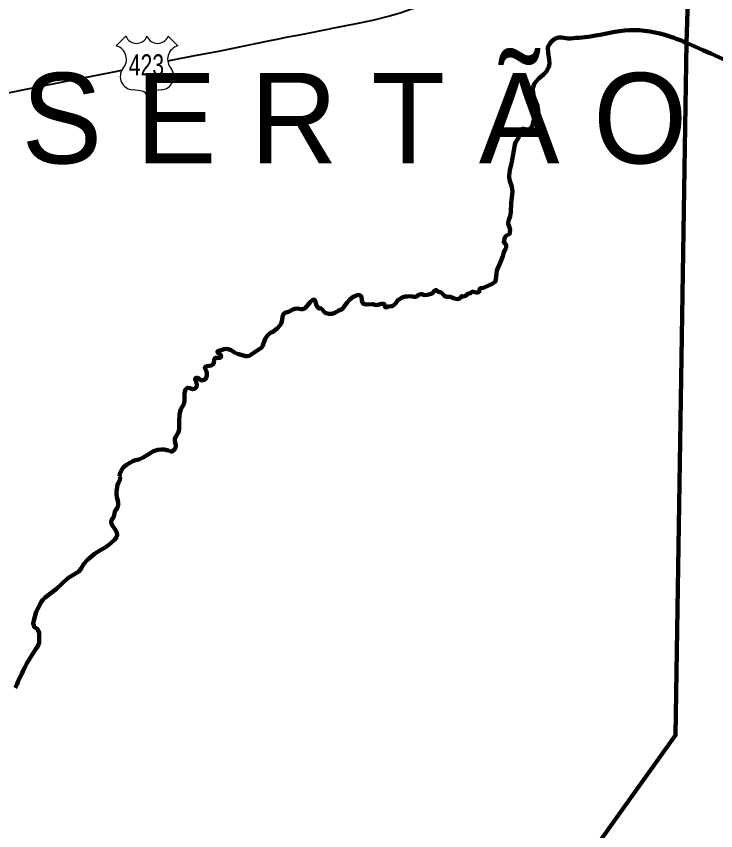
# Model space of a CAD drawing. Extents: x 553962 to 842807, y 8883888 to 9032388.
# Drawn here: x 626151 to 637742, y 8959925 to 8973416 of the extents above; entities that cross this region are included whole.
import ezdxf
from ezdxf.enums import TextEntityAlignment as Align

# ---------------------------------------------------------------- set-up
doc = ezdxf.new("R2010")
doc.units = 0
doc.header["$LTSCALE"] = 200
for name, color, linetype, lineweight in [('12', 7, 'Continuous', 25), ('24', 7, 'Continuous', 25), ('48', 7, 'Continuous', 25), ('9', 7, 'Continuous', 90)]:
    doc.layers.add(name, color=color, linetype=linetype, lineweight=lineweight)
doc.layers.add('13', color=7, linetype='Continuous')

msp = doc.modelspace()

# ---------------------------------------------------------------- linework, layer by layer
at = {"layer": '12', "lineweight": 40}
for points in [[(636526.5, 8974783.6), (636082.7, 8974635.6), (635662.2, 8974501.7), (635260.8, 8974371.9), (634884.1, 8974246.1), (634508.7, 8974119.3), (634143, 8973999.6), (633777.1, 8973878.8), (633411.3, 8973759), (633045.5, 8973640.3), (632701.6, 8973531.6), (632515, 8973468.2), (632359.8, 8973423.8), (632056.8, 8973345.2), (631756.7, 8973285.7), (631470.2, 8973228.1), (631226.1, 8973179.7), (631010.7, 8973135.2), (630810.4, 8973099.9), (630618.3, 8973063.5), (630498.6, 8973037.3), (630299.5, 8972998.9)], [(630299.5, 8972998.9), (629900.9, 8972917.2), (629502.3, 8972835.4), (629106.4, 8972761.7), (628714.6, 8972683.9), (628658.2, 8972671.9)], [(627892.1, 8972517.3), (627787.3, 8972497.2), (626527.3, 8972247.8), (625278.3, 8971995.4), (625208.3, 8971975.3), (624859.1, 8971919.6), (624586.2, 8971856.1), (624327.1, 8971807.6), (624078.9, 8971766.2), (623877.2, 8971718.8), (623688.2, 8971682.4)]]:
    msp.add_lwpolyline(points, dxfattribs=at)
at = {"layer": '24'}
for points in [[(635289.1, 8973046.9), (635193.3, 8973064.8), (635152.3, 8973065.7), (635121.8, 8973060.6), (635088.4, 8973049.6), (635061.3, 8973033.5), (635024.5, 8973002.4), (634997.2, 8972972.3), (634966.1, 8972918.2), (634961, 8972900.1), (634963.3, 8972809), (634982.5, 8972700.9), (634988.3, 8972634.8), (634977.1, 8972576.7), (634957, 8972536.6), (634931, 8972498.5), (634893.6, 8972457.3), (634810.8, 8972383.1), (634757.5, 8972324.9), (634734.8, 8972291.8), (634721.1, 8972258.8), (634713.2, 8972225.7), (634711, 8972195.6), (634723.7, 8972103.5), (634738.5, 8972051.5), (634787.3, 8971934.3), (634802.1, 8971867.3), (634801, 8971826.2), (634787, 8971787.1), (634735.3, 8971720.9), (634725.3, 8971693.9), (634707.4, 8971613.7), (634694.8, 8971588.7), (634670.6, 8971557.6), (634653, 8971546.5), (634625.3, 8971541.5), (634559.7, 8971552.4), (634539.5, 8971553.4), (634505.6, 8971527.3), (634489.3, 8971482.2), (634473.5, 8971402), (634424.6, 8971322.8), (634411, 8971288.8), (634363.8, 8971005.2), (634331.5, 8970867), (634319.9, 8970779.8), (634321.1, 8970743.8), (634328.9, 8970692.7), (634361.6, 8970589.6), (634374.7, 8970513.5), (634371.4, 8970461.4), (634350, 8970323.2), (634349.1, 8970169.9), (634336.1, 8970107.8), (634312.2, 8970046.7), (634303.6, 8970002.6), (634304.6, 8969985.6), (634333.8, 8969882.4), (634332.9, 8969828.3), (634324.3, 8969808.3), (634272.2, 8969782.2), (634248.5, 8969757.1), (634230.1, 8969676), (634268.6, 8969630), (634268.6, 8969569.3)], [(634268.6, 8969569.3), (634244.3, 8969539), (634226.1, 8969484.3), (634214, 8969441.9), (634171.5, 8969332.7), (634116.8, 8969205.3), (634098.6, 8969053.6), (634086.5, 8969017.2), (634039.3, 8968984.8)], [(634039.3, 8968984.8), (633892.2, 8968920.1), (633841.2, 8968911.2), (633829, 8968894.2), (633826.5, 8968860.1), (633814.7, 8968848.1), (633792.7, 8968839.1), (633772.6, 8968838), (633707.3, 8968856), (633679.2, 8968828.9), (633643, 8968822.8), (633597.4, 8968783.7), (633572.7, 8968776.6), (633532.2, 8968781.6), (633506.6, 8968748.5), (633477, 8968733.4), (633461.8, 8968732.4), (633415.1, 8968740.3), (633342.3, 8968771.2), (633285, 8968769.1), (633251.4, 8968778.1), (633194.6, 8968839.1), (633136, 8968858.1), (633110.7, 8968880), (633099.8, 8968882), (633077.7, 8968869), (633061.8, 8968841.9), (633034, 8968818.8), (632961, 8968800.7), (632917, 8968797.6), (632873.8, 8968812.6), (632857.7, 8968813.5), (632829.5, 8968806.5), (632784.3, 8968774.4), (632762.5, 8968768.3), (632743.5, 8968767.3), (632689.7, 8968778.2), (632635, 8968777.1), (632594.3, 8968772.1), (632546, 8968759), (632474, 8968715.8), (632441.1, 8968661.6), (632402.4, 8968626.5), (632375.7, 8968616.5), (632320, 8968608.4), (632276, 8968592.3), (632267.3, 8968594.3), (632260.3, 8968604.3), (632251.7, 8968645.3), (632234.7, 8968652.3), (632204.8, 8968654.2), (632145, 8968637.1), (632109, 8968631.1), (632058.6, 8968648), (631959.9, 8968641.8), (631914.2, 8968649.8), (631895.5, 8968662.8), (631887.1, 8968674.8), (631878, 8968708.8), (631869.8, 8968767.9), (631863.3, 8968783.9), (631842.8, 8968796.9), (631814.7, 8968800.9), (631735.7, 8968766.7), (631677.1, 8968724.5), (631636.5, 8968676.4), (631586.8, 8968606.2)], [(631586.8, 8968606.2), (631586.8, 8968606.2), (631566, 8968583.1), (631538.7, 8968561.1), (631495.2, 8968543), (631432.7, 8968503.8), (631386.3, 8968486.7), (631328.7, 8968484.6), (631284.8, 8968496.6), (631269.3, 8968505.5), (631202.2, 8968575.6), (631191.8, 8968578.5), (631168.3, 8968573.5), (631157.2, 8968578.5), (631126.3, 8968623.5), (631111.8, 8968681.6), (631101.9, 8968706.6), (631091.9, 8968716.6), (631075.5, 8968722.6), (631055.8, 8968713.5), (631019.8, 8968680.4), (630944.5, 8968589.2), (630924.7, 8968575.1), (630898.9, 8968567.1), (630870.7, 8968563), (630810.1, 8968573.9), (630771.4, 8968571.9), (630733.8, 8968558.8), (630662, 8968521.6), (630604.2, 8968505.5), (630582.5, 8968486.4), (630570.5, 8968464.4), (630552, 8968360.2), (630538.6, 8968328.1), (630519, 8968295), (630475.5, 8968245.9), (630400.9, 8968188.7), (630373.3, 8968178.6), (630353.6, 8968166.6), (630308.6, 8968122.4), (630276.4, 8968071.3), (630238.3, 8967960.1), (630219.6, 8967931), (630204, 8967915.9), (630110, 8967856.7), (630037.7, 8967805.5), (630008, 8967791.4), (629973.1, 8967784.4), (629952.7, 8967785.3), (629818.6, 8967822.2), (629765.8, 8967848.1), (629713, 8967885.1), (629664.5, 8967904.1), (629633.8, 8967907), (629598, 8967904), (629531.5, 8967879.8), (629496.2, 8967871.8), (629483.7, 8967859.7), (629486.2, 8967847.7), (629492.6, 8967840.7), (629540.7, 8967810.7), (629545.3, 8967784.7), (629540.8, 8967768.7), (629532.8, 8967760.6), (629522.4, 8967757.6), (629462.2, 8967760.5), (629444.6, 8967756.5), (629432.2, 8967733.4), (629423.8, 8967670.3), (629408.2, 8967648.3), (629382.3, 8967632.2), (629313.2, 8967622.1), (629285.3, 8967611), (629277.8, 8967603), (629278.1, 8967588), (629305.3, 8967533.9), (629310.7, 8967502.9), (629308.8, 8967461.8), (629293.1, 8967414.7), (629266.5, 8967393.6), (629234, 8967384.6), (629199.3, 8967395.5), (629158.3, 8967424.5), (629139.8, 8967426.5), (629123.2, 8967422.5), (629117.6, 8967414.4), (629118, 8967394.4), (629139.5, 8967343.4), (629144.7, 8967309.3), (629140.5, 8967289.3), (629122.5, 8967256.2), (629103.3, 8967245.2), (629075.3, 8967238.1), (629026.3, 8967257.1), (628994.8, 8967264), (628978.7, 8967255), (628957.3, 8967232.9), (628940.9, 8967175.8), (628937.1, 8967045.6), (628928.9, 8966993.5), (628879.5, 8966907.3)], [(628879.5, 8966907.3), (628856.2, 8966825.1), (628856.2, 8966825.1), (628847.9, 8966696.9), (628850.9, 8966584.7), (628846.8, 8966548.7), (628833.2, 8966513.6), (628795.6, 8966457.4), (628777.8, 8966417.3), (628777.8, 8966370.3), (628794.8, 8966312.2), (628795, 8966279.2), (628772.4, 8966240.1), (628724.9, 8966202.9), (628672.1, 8966222.8)], [(628672.1, 8966222.8), (628644.5, 8966231.7), (628607, 8966237.7), (628560.1, 8966237.6), (628499.1, 8966232.5), (628424.4, 8966210.3), (628380.7, 8966187.2), (628295.1, 8966129), (628244.3, 8966100.9), (628182.1, 8966074.8), (628126, 8966063.7), (628091.9, 8966052.6), (628032.2, 8966021.4), (627977.3, 8965986.3), (627925.1, 8965941.1), (627901.8, 8965910.1), (627866.5, 8965837.9), (627864.4, 8965796.7)], [(627864.4, 8965796.7), (627870.8, 8965773.8), (627867.2, 8965732.7), (627839, 8965684.6), (627827.1, 8965654.5), (627811.8, 8965541.3), (627811.5, 8965505.3), (627817.4, 8965449.2), (627838.1, 8965372.1), (627841, 8965321), (627826.7, 8965271.9), (627798.1, 8965236.8), (627783.4, 8965207.8), (627766.8, 8965123.6), (627733.2, 8965082.5), (627726.4, 8965067.5), (627723.3, 8965046.4), (627728.3, 8965015.4), (627739.7, 8964986.4), (627792.5, 8964916.3), (627811.7, 8964876.3), (627823.6, 8964830.2), (627816, 8964796.2)], [(627816, 8964796.2), (627816, 8964796.2), (627780.2, 8964746.1), (627680.5, 8964655.8), (627612, 8964609.6), (627536.8, 8964566.4), (627449.5, 8964509.2), (627333.7, 8964414.8), (627272.4, 8964348.6), (627225, 8964267.4), (627185.5, 8964217.3), (627032.1, 8964127.9), (627004.7, 8964107.8), (626815.8, 8963934.3), (626629.8, 8963789.7), (626590.1, 8963751.6), (626566.7, 8963720.5), (626506, 8963608.3), (626480.1, 8963551.1), (626439.9, 8963406.8), (626430.6, 8963358.8), (626441.2, 8963331.8), (626448.8, 8963299.7), (626457.1, 8963293.7), (626491.3, 8963272.5), (626505.7, 8963251), (626515.9, 8963242.8), (626529.7, 8963201.7), (626531.3, 8963131.3), (626529.2, 8963109.8), (626529.5, 8963038.6), (626501.7, 8962971.9), (626473.9, 8962938.6), (626318.3, 8962688.6), (626296, 8962638.6), (626262.7, 8962577.5), (626240.4, 8962522), (626212.7, 8962460.8), (626174.8, 8962393.8), (626164.1, 8962350.8), (626134.9, 8962291.6)]]:
    msp.add_lwpolyline(points, dxfattribs=at)
at = {"layer": '48'}
for p, q in [((627808.4, 8972926.9), (627968.3, 8973086.8)), ((628667.7, 8973086.8), (628827.6, 8972926.9))]:
    msp.add_line(p, q, dxfattribs=at)
for centre, radius, start, end in [((628143.2, 8973153.7), 187.2, 200.95927, 339.04073), ((628492.8, 8973153.7), 187.2, 200.95927, 339.04073), ((627746.3, 8972705), 230.3, 317.5721, 74.36886), ((628889.7, 8972705), 230.3, 105.62774, 222.4279), ((628099.8, 8972419.9), 224.7, 144.73733, 264.65778), ((628536.2, 8972419.9), 224.7, 275.34222, 35.26267), ((628077.9, 8971606.4), 589.7, 72.89371, 89.90057), ((628558.1, 8971606.4), 589.7, 90.09943, 107.10629), ((628223.6, 8972079.8), 94.4, 357.69345, 72.92955), ((628412.4, 8972079.8), 94.4, 107.07045, 182.30655)]:
    msp.add_arc(centre, radius, start, end, dxfattribs=at)
at = {"layer": '9'}
for points in [[(637260.6, 8972975.8), (637390.8, 8977204.2), (635350.7, 8977923.9), (623791.9, 8983133)], [(635289.1, 8973046.9), (635193.3, 8973064.8), (635152.3, 8973065.7), (635121.8, 8973060.6), (635088.4, 8973049.6), (635061.3, 8973033.5), (635024.5, 8973002.4), (634997.2, 8972972.3), (634966.1, 8972918.2), (634961, 8972900.1), (634963.3, 8972809), (634982.5, 8972700.9), (634988.3, 8972634.8), (634977.1, 8972576.7), (634957, 8972536.6), (634931, 8972498.5), (634893.6, 8972457.3), (634810.8, 8972383.1), (634757.5, 8972324.9), (634734.8, 8972291.8), (634721.1, 8972258.8), (634713.2, 8972225.7), (634711, 8972195.6), (634723.7, 8972103.5), (634738.5, 8972051.5), (634787.3, 8971934.3), (634802.1, 8971867.3), (634801, 8971826.2), (634787, 8971787.1), (634735.3, 8971720.9), (634725.3, 8971693.9), (634707.4, 8971613.7), (634694.8, 8971588.7), (634670.6, 8971557.6), (634653, 8971546.5), (634625.3, 8971541.5), (634559.7, 8971552.4), (634539.5, 8971553.4), (634505.6, 8971527.3), (634489.3, 8971482.2), (634473.5, 8971402), (634424.6, 8971322.8), (634411, 8971288.8), (634363.8, 8971005.2), (634331.5, 8970867), (634319.9, 8970779.8), (634321.1, 8970743.8), (634328.9, 8970692.7), (634361.6, 8970589.6), (634374.7, 8970513.5), (634371.4, 8970461.4), (634350, 8970323.2), (634349.1, 8970169.9), (634336.1, 8970107.8), (634312.2, 8970046.7), (634303.6, 8970002.6), (634304.6, 8969985.6), (634333.8, 8969882.4), (634332.9, 8969828.3), (634324.3, 8969808.3), (634272.2, 8969782.2), (634248.5, 8969757.1), (634230.1, 8969676), (634268.6, 8969630), (634268.6, 8969569.3)], [(637260.6, 8972975.8), (637076.8, 8961505.7), (634855.7, 8958401.3), (634875.3, 8955110.3)], [(634268.6, 8969569.3), (634244.3, 8969539), (634226.1, 8969484.3), (634214, 8969441.9), (634171.5, 8969332.7), (634116.8, 8969205.3), (634098.6, 8969053.6), (634086.5, 8969017.2), (634039.3, 8968984.8)], [(634039.3, 8968984.8), (633892.2, 8968920.1), (633841.2, 8968911.2), (633829, 8968894.2), (633826.5, 8968860.1), (633814.7, 8968848.1), (633792.7, 8968839.1), (633772.6, 8968838), (633707.3, 8968856), (633679.2, 8968828.9), (633643, 8968822.8), (633597.4, 8968783.7), (633572.7, 8968776.6), (633532.2, 8968781.6), (633506.6, 8968748.5), (633477, 8968733.4), (633461.8, 8968732.4), (633415.1, 8968740.3), (633342.3, 8968771.2), (633285, 8968769.1), (633251.4, 8968778.1), (633194.6, 8968839.1), (633136, 8968858.1), (633110.7, 8968880), (633099.8, 8968882), (633077.7, 8968869), (633061.8, 8968841.9), (633034, 8968818.8), (632961, 8968800.7), (632917, 8968797.6), (632873.8, 8968812.6), (632857.7, 8968813.5), (632829.5, 8968806.5), (632784.3, 8968774.4), (632762.5, 8968768.3), (632743.5, 8968767.3), (632689.7, 8968778.2), (632635, 8968777.1), (632594.3, 8968772.1), (632546, 8968759), (632474, 8968715.8), (632441.1, 8968661.6), (632402.4, 8968626.5), (632375.7, 8968616.5), (632320, 8968608.4), (632276, 8968592.3), (632267.3, 8968594.3), (632260.3, 8968604.3), (632251.7, 8968645.3), (632234.7, 8968652.3), (632204.8, 8968654.2), (632145, 8968637.1), (632109, 8968631.1), (632058.6, 8968648), (631959.9, 8968641.8), (631914.2, 8968649.8), (631895.5, 8968662.8), (631887.1, 8968674.8), (631878, 8968708.8), (631869.8, 8968767.9), (631863.3, 8968783.9), (631842.8, 8968796.9), (631814.7, 8968800.9), (631735.7, 8968766.7), (631677.1, 8968724.5), (631636.5, 8968676.4), (631586.8, 8968606.2)], [(631586.8, 8968606.2), (631586.8, 8968606.2), (631566, 8968583.1), (631538.7, 8968561.1), (631495.2, 8968543), (631432.7, 8968503.8), (631386.3, 8968486.7), (631328.7, 8968484.6), (631284.8, 8968496.6), (631269.3, 8968505.5), (631202.2, 8968575.6), (631191.8, 8968578.5), (631168.3, 8968573.5), (631157.2, 8968578.5), (631126.3, 8968623.5), (631111.8, 8968681.6), (631101.9, 8968706.6), (631091.9, 8968716.6), (631075.5, 8968722.6), (631055.8, 8968713.5), (631019.8, 8968680.4), (630944.5, 8968589.2), (630924.7, 8968575.1), (630898.9, 8968567.1), (630870.7, 8968563), (630810.1, 8968573.9), (630771.4, 8968571.9), (630733.8, 8968558.8), (630662, 8968521.6), (630604.2, 8968505.5), (630582.5, 8968486.4), (630570.5, 8968464.4), (630552, 8968360.2), (630538.6, 8968328.1), (630519, 8968295), (630475.5, 8968245.9), (630400.9, 8968188.7), (630373.3, 8968178.6), (630353.6, 8968166.6), (630308.6, 8968122.4), (630276.4, 8968071.3), (630238.3, 8967960.1), (630219.6, 8967931), (630204, 8967915.9), (630110, 8967856.7), (630037.7, 8967805.5), (630008, 8967791.4), (629973.1, 8967784.4), (629952.7, 8967785.3), (629818.6, 8967822.2), (629765.8, 8967848.1), (629713, 8967885.1), (629664.5, 8967904.1), (629633.8, 8967907), (629598, 8967904), (629531.5, 8967879.8), (629496.2, 8967871.8), (629483.7, 8967859.7), (629486.2, 8967847.7), (629492.6, 8967840.7), (629540.7, 8967810.7), (629545.3, 8967784.7), (629540.8, 8967768.7), (629532.8, 8967760.6), (629522.4, 8967757.6), (629462.2, 8967760.5), (629444.6, 8967756.5), (629432.2, 8967733.4), (629423.8, 8967670.3), (629408.2, 8967648.3), (629382.3, 8967632.2), (629313.2, 8967622.1), (629285.3, 8967611), (629277.8, 8967603), (629278.1, 8967588), (629305.3, 8967533.9), (629310.7, 8967502.9), (629308.8, 8967461.8), (629293.1, 8967414.7), (629266.5, 8967393.6), (629234, 8967384.6), (629199.3, 8967395.5), (629158.3, 8967424.5), (629139.8, 8967426.5), (629123.2, 8967422.5), (629117.6, 8967414.4), (629118, 8967394.4), (629139.5, 8967343.4), (629144.7, 8967309.3), (629140.5, 8967289.3), (629122.5, 8967256.2), (629103.3, 8967245.2), (629075.3, 8967238.1), (629026.3, 8967257.1), (628994.8, 8967264), (628978.7, 8967255), (628957.3, 8967232.9), (628940.9, 8967175.8), (628937.1, 8967045.6), (628928.9, 8966993.5), (628879.5, 8966907.3)], [(628879.5, 8966907.3), (628856.2, 8966825.1), (628856.2, 8966825.1), (628847.9, 8966696.9), (628850.9, 8966584.7), (628846.8, 8966548.7), (628833.2, 8966513.6), (628795.6, 8966457.4), (628777.8, 8966417.3), (628777.8, 8966370.3), (628794.8, 8966312.2), (628795, 8966279.2), (628772.4, 8966240.1), (628724.9, 8966202.9), (628672.1, 8966222.8)], [(628672.1, 8966222.8), (628644.5, 8966231.7), (628607, 8966237.7), (628560.1, 8966237.6), (628499.1, 8966232.5), (628424.4, 8966210.3), (628380.7, 8966187.2), (628295.1, 8966129), (628244.3, 8966100.9), (628182.1, 8966074.8), (628126, 8966063.7), (628091.9, 8966052.6), (628032.2, 8966021.4), (627977.3, 8965986.3), (627925.1, 8965941.1), (627901.8, 8965910.1), (627866.5, 8965837.9), (627864.4, 8965796.7)], [(627864.4, 8965796.7), (627870.8, 8965773.8), (627867.2, 8965732.7), (627839, 8965684.6), (627827.1, 8965654.5), (627811.8, 8965541.3), (627811.5, 8965505.3), (627817.4, 8965449.2), (627838.1, 8965372.1), (627841, 8965321), (627826.7, 8965271.9), (627798.1, 8965236.8), (627783.4, 8965207.8), (627766.8, 8965123.6), (627733.2, 8965082.5), (627726.4, 8965067.5), (627723.3, 8965046.4), (627728.3, 8965015.4), (627739.7, 8964986.4), (627792.5, 8964916.3), (627811.7, 8964876.3), (627823.6, 8964830.2), (627816, 8964796.2)], [(627816, 8964796.2), (627816, 8964796.2), (627780.2, 8964746.1), (627680.5, 8964655.8), (627612, 8964609.6), (627536.8, 8964566.4), (627449.5, 8964509.2), (627333.7, 8964414.8), (627272.4, 8964348.6), (627225, 8964267.4), (627185.5, 8964217.3), (627032.1, 8964127.9), (627004.7, 8964107.8), (626815.8, 8963934.3), (626629.8, 8963789.7), (626590.1, 8963751.6), (626566.7, 8963720.5), (626506, 8963608.3), (626480.1, 8963551.1), (626439.9, 8963406.8), (626430.6, 8963358.8), (626441.2, 8963331.8), (626448.8, 8963299.7), (626457.1, 8963293.7), (626491.3, 8963272.5), (626505.7, 8963251), (626515.9, 8963242.8), (626529.7, 8963201.7), (626531.3, 8963131.3), (626529.2, 8963109.8), (626529.5, 8963038.6), (626501.7, 8962971.9), (626473.9, 8962938.6), (626318.3, 8962688.6), (626296, 8962638.6), (626262.7, 8962577.5), (626240.4, 8962522), (626212.7, 8962460.8), (626174.8, 8962393.8), (626164.1, 8962350.8), (626134.9, 8962291.6)]]:
    msp.add_lwpolyline(points, dxfattribs=at)
for points in [[(637260.6, 8972975.8), (636979.7, 8973082.7), (636310.5, 8973184.6), (635667.8, 8973082.7), (635289.1, 8973046.9)], [(637260.6, 8972975.8), (641524.5, 8971056.2), (652526.1, 8965412.7), (653164.3, 8965062.8), (670790.5, 8953770.1), (686194, 8943929.9), (696283.3, 8937647.1)]]:
    msp.add_spline(points, degree=3, dxfattribs=at)

# ---------------------------------------------------------------- texts
at = {"layer": '13'}
msp.add_text('S E R T Ã O', height=1500, dxfattribs=at).set_placement((631754.6, 8970978.7), align=Align.CENTER)
at = {"layer": '48', "width": 0.75}
msp.add_text('423', height=350, dxfattribs=at).set_placement((628307.7, 8972435.3), align=Align.CENTER)

doc.saveas('drawing.dxf')
